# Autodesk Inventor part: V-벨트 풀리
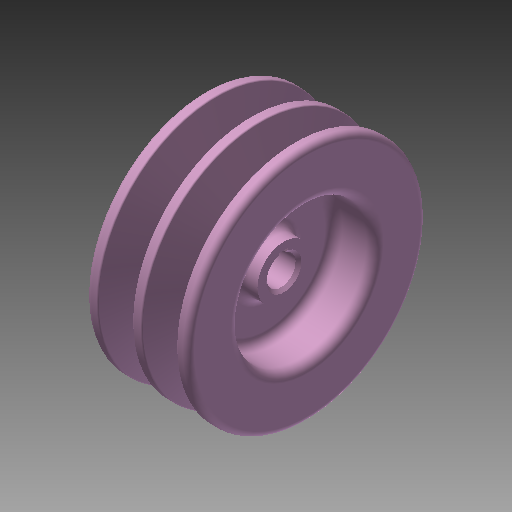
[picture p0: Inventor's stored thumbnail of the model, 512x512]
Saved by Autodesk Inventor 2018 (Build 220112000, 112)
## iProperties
Created: 2024-01
Part Number: V-벨트 풀리
Material: 강철, 주조
Document SubType Name: Modeling
Designer: mdu-01
Density: 1 g/cm^3
Appearance: 기본값(1)
Author: mdu-01
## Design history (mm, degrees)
sketch "스케치1"
  geometry: L1 (-9.5, 0)-(9.5, 0); L2 (-9.5, 6)-(-9.5, 9); L3 (-9.5, 9)-(-6.5, 9); L4 (-3.5, 12)-(-3.5, 20); L5 (-6.5, 23)-(-14.5, 23); L6 (-17.5, 26)-(-17.5, 38.5); L7 (0, 0)-(0, 40.5); L8 (9.5, 9)-(6.5, 9); L9 (9.5, 6)-(9.5, 9); L10 (3.5, 12)-(3.5, 20); L11 (6.5, 23)-(14.5, 23); L12 (17.5, 26)-(17.5, 38.5); L13 (-8.5, 5)-(8.5, 5); L14 (-9.5, 6)-(-8.5, 5); L15 (9.5, 6)-(8.5, 5); L16 (-7.5, 40.5)-(-7.5, 28); L17 (-13.368, 40.146)-(-9.87, 28.708); L18 (-1.632, 40.146)-(-5.13, 28.708); L19 (-8.914, 28)-(-6.086, 28); L20 (-15.5, 40.5)-(-13.846, 40.5); L21 (8.914, 28)-(6.086, 28); L22 (1.632, 40.146)-(5.13, 28.708); L23 (13.368, 40.146)-(9.87, 28.708); L24 (-1.154, 40.5)-(1.154, 40.5); L25 (13.846, 40.5)-(15.5, 40.5); A1 r 3 centre (-6.5, 12) between (-6.5, 9) and (-3.5, 12); A2 r 3 centre (-6.5, 20) between (-3.5, 20) and (-6.5, 23); A3 r 3 centre (-14.5, 26) between (-17.5, 26) and (-14.5, 23); A4 r 2 centre (-15.5, 38.5) between (-15.5, 40.5) and (-17.5, 38.5); A5 r 3 centre (6.5, 12) between (3.5, 12) and (6.5, 9); A6 r 3 centre (6.5, 20) between (6.5, 23) and (3.5, 20); A7 r 2 centre (15.5, 38.5) between (17.5, 38.5) and (15.5, 40.5); A8 r 3 centre (14.5, 26) between (14.5, 23) and (17.5, 26); A9 r 1 centre (-8.914, 29) between (-9.87, 28.708) and (-8.914, 28); A10 r 1 centre (-6.086, 29) between (-6.086, 28) and (-5.13, 28.708); A11 r 0.5 centre (-13.846, 40) between (-13.368, 40.146) and (-13.846, 40.5); A12 r 0.5 centre (-1.154, 40) between (-1.154, 40.5) and (-1.632, 40.146); A13 r 0.5 centre (1.154, 40) between (1.632, 40.146) and (1.154, 40.5); A14 r 1 centre (6.086, 29) between (5.13, 28.708) and (6.086, 28); A15 r 1 centre (8.914, 29) between (8.914, 28) and (9.87, 28.708); A16 r 0.5 centre (13.846, 40) between (13.846, 40.5) and (13.368, 40.146); 12 further points
  constraints: 50 end point, 32 point on circle, 32 symmetric about line, 19 point on line, 19 tangent, 16 centre point, 8 perpendicular, 6 parallel, 4 equal radius, 3 midpoint, 1 coincident, 1 horizontal, 8 other
  dimensions: "d0" = 19 distance of L1.start L1.end; "d1" = 3 radius of A1; "d2" = 2 radius of A4; "d3" = 18 diameter of L3 L1; "d4" = 10 diameter of L13 L1; "d5" = 1 distance of L2.start point (-9.5, 5); "d6" = 1 distance of L13.start point (-9.5, 5) (= d5); "d7" = 1 distance of L9.start point (9.5, 5) (= d5); "d8" = 1 distance of L13.end point (9.5, 5) (= d7); "d9" = 7 distance between parallel lines of L10 L4; "d10" = 46 diameter of L5 L1; "d11" = 35 distance between parallel lines of L12 L6; "d13" = 72 diameter of point (-12.1, 36) L1; "d14" = 34 deg angle of L18 L17; "d15" = 9.2 diameter of point (-12.1, 36) L16; "d16" = 15 diameter of L16 L7; "d17" = 8 distance from line of L19 point (-12.1, 36); "d18" = 4.5 distance from line of L20 point (-12.1, 36); "d19" = 1 radius of A9; "d20" = 0.5 radius of A11
revolve "회전1" sketch "스케치1" stored, may be unused: angle "d21" = 90 deg
sketch "스케치2"
  geometry: L1 (-1.5, 4.77)-(1.5, 4.77); L2 (1.5, 4.77)-(1.5, 6.4); L3 (1.5, 6.4)-(-1.5, 6.4); L4 (-1.5, 6.4)-(-1.5, 4.77); A1 r 5 centre (0, 0) between (-1.5, 4.77) and (1.5, 4.77) reference; 2 further points
  constraints: 8 end point, 3 point on circle, 2 parallel, 1 horizontal, 1 perpendicular, 1 vertical alignment
  dimensions: "d22" = 3 distance between parallel lines of L2 L4; "d24" = 11.4 distance from line of point (0, -5) L3
extrude "돌출1" cut sketch "스케치2" extent not by distance; stored distance "d25" = 10; taper "d26" = 0 deg
node "솔리드1"
other parameters: "d12" = 81
